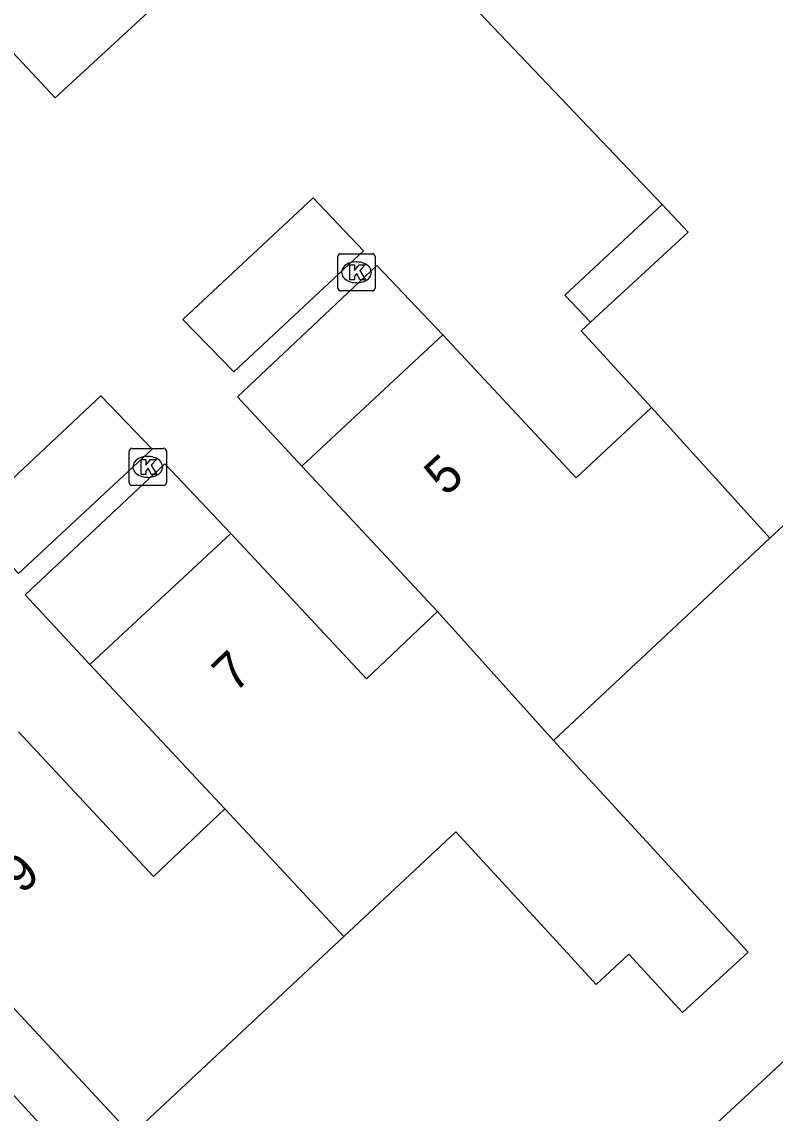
# Model space of a CAD drawing. Extents: x 160664 to 161506, y 382245 to 383288.
# Drawn here: x 160794.56 to 160814.82, y 383002.22 to 383031.57 of the extents above; entities that cross this region are included whole.
import ezdxf

# ---------------------------------------------------------------- set-up
doc = ezdxf.new("R2010")
doc.units = 0
for name, color, linetype in [('IMGEO_Fietspad_gesloten', 7, 'Continuous'), ('IMGEO_Kolk', 7, 'Continuous'), ('IMGEO_Pand', 7, 'Continuous'), ('IMGEO_Pand_nummerreeks', 7, 'Continuous'), ('IMGEO_Rijbaan_lokaal_open', 7, 'Continuous'), ('IMGEO_Voetpad_open', 7, 'Continuous')]:
    doc.layers.add(name, color=color, linetype=linetype)

msp = doc.modelspace()

# ---------------------------------------------------------------- linework, layer by layer
at = {"layer": 'IMGEO_Fietspad_gesloten'}
msp.add_lwpolyline([(160777.267, 383021.287), (160830.559, 382963.235), (160831.457, 382962.256), (160842.206, 382950.625)], dxfattribs=at)
at = {"layer": 'IMGEO_Kolk'}
for p, q in [((160803.057, 383024.411), (160803.057, 383025.263)), ((160803.132, 383025.337), (160803.984, 383025.337)), ((160804.058, 383025.263), (160804.058, 383024.411)), ((160803.545, 383025.117), (160803.57, 383025.117)), ((160803.984, 383024.337), (160803.132, 383024.337)), ((160803.568, 383024.557), (160803.543, 383024.557)), ((160797.443, 383019.177), (160797.443, 383020.029)), ((160797.518, 383020.103), (160798.37, 383020.103)), ((160798.444, 383020.029), (160798.444, 383019.177)), ((160797.931, 383019.883), (160797.956, 383019.883)), ((160797.954, 383019.323), (160797.929, 383019.323)), ((160798.37, 383019.103), (160797.518, 383019.103))]:
    msp.add_line(p, q, dxfattribs=at)
for points in [[(160803.057, 383024.411), (160803.057, 383025.263)], [(160803.132, 383025.337), (160803.984, 383025.337)], [(160804.058, 383025.263), (160804.058, 383024.411)], [(160803.378, 383025.037), (160803.501, 383025.037), (160803.501, 383024.886), (160803.631, 383025.037), (160803.795, 383025.037), (160803.649, 383024.886), (160803.802, 383024.637), (160803.65, 383024.637), (160803.565, 383024.801), (160803.501, 383024.734), (160803.501, 383024.637), (160803.378, 383024.637), (160803.378, 383025.037)], [(160803.984, 383024.337), (160803.132, 383024.337)], [(160797.443, 383019.177), (160797.443, 383020.029)], [(160797.518, 383020.103), (160798.37, 383020.103)], [(160798.444, 383020.029), (160798.444, 383019.177)], [(160797.764, 383019.803), (160797.887, 383019.803), (160797.887, 383019.652), (160798.017, 383019.803), (160798.181, 383019.803), (160798.035, 383019.652), (160798.188, 383019.403), (160798.036, 383019.403), (160797.951, 383019.567), (160797.887, 383019.5), (160797.887, 383019.403), (160797.764, 383019.403), (160797.764, 383019.803)], [(160798.37, 383019.103), (160797.518, 383019.103)]]:
    msp.add_lwpolyline(points, dxfattribs=at)
for centre, start, end in [((160803.134, 383025.261), 91.552, 178.448), ((160803.134, 383025.261), 91.552, 178.448), ((160803.982, 383025.261), 1.552, 88.448), ((160803.982, 383025.261), 1.552, 88.448), ((160803.134, 383024.413), 181.552, 268.448), ((160803.134, 383024.413), 181.552, 268.448), ((160803.982, 383024.413), 271.552, 358.448), ((160803.982, 383024.413), 271.552, 358.448), ((160797.52, 383020.027), 91.552, 178.448), ((160797.52, 383020.027), 91.552, 178.448), ((160798.368, 383020.027), 1.552, 88.448), ((160798.368, 383020.027), 1.552, 88.448), ((160797.52, 383019.179), 181.552, 268.448), ((160797.52, 383019.179), 181.552, 268.448), ((160798.368, 383019.179), 271.552, 358.448), ((160798.368, 383019.179), 271.552, 358.448)]:
    msp.add_arc(centre, 0.0765, start, end, dxfattribs=at)
for centre, major_axis, ratio, start_param, end_param in [((160803.544, 383024.837), (-0.387, 0.002), 0.722429, 4.712389, 7.853982), ((160803.569, 383024.837), (-0.39, 0.002), 0.717154, 1.570796, 4.712389), ((160797.93, 383019.603), (-0.387, 0.002), 0.722429, 4.712389, 7.853982), ((160797.955, 383019.603), (-0.39, 0.002), 0.717154, 1.570796, 4.712389)]:
    msp.add_ellipse(centre, major_axis=major_axis, ratio=ratio, start_param=start_param, end_param=end_param, dxfattribs=at)
at = {"layer": 'IMGEO_Pand'}
for points in [[(160798.881, 383040.207), (160811.78, 383026.66)], [(160814.674, 383017.683), (160815.277, 383018.246), (160815.072, 383018.458), (160826.068, 383028.889), (160823.688, 383031.397), (160824.264, 383031.944)], [(160811.78, 383026.66), (160812.484, 383025.921), (160809.853, 383023.497)], [(160809.853, 383023.497), (160809.603, 383023.267), (160811.497, 383021.202)], [(160805.883, 383023.157), (160802.091, 383019.626)], [(160811.497, 383021.202), (160809.467, 383019.307), (160805.883, 383023.157)], [(160811.497, 383021.202), (160814.674, 383017.683)], [(160802.091, 383019.626), (160805.737, 383015.711)], [(160800.177, 383017.817), (160796.388, 383014.288)], [(160805.737, 383015.711), (160803.824, 383013.902), (160800.177, 383017.817)], [(160808.861, 383012.25), (160814.674, 383017.683)], [(160805.737, 383015.711), (160808.861, 383012.25)], [(160796.388, 383014.288), (160800.016, 383010.405)], [(160800.016, 383010.405), (160798.097, 383008.591), (160794.468, 383012.481)], [(160808.861, 383012.25), (160811.566, 383009.303), (160812.633, 383008.14), (160814.093, 383006.549), (160812.326, 383004.927), (160810.88, 383006.502), (160810.002, 383005.682), (160808.935, 383006.845), (160806.23, 383009.792), (160803.219, 383006.978)], [(160803.219, 383006.978), (160800.016, 383010.405)], [(160797.509, 383001.643), (160790.688, 383008.954)], [(160803.219, 383006.978), (160797.729, 383001.848)]]:
    msp.add_lwpolyline(points, dxfattribs=at)
at = {"layer": 'IMGEO_Rijbaan_lokaal_open'}
for points in [[(160795.873, 383036.094), (160792.283, 383032.916), (160795.455, 383029.533), (160798.981, 383032.794), (160797.262, 383034.672)], [(160803.749, 383025.412), (160802.392, 383026.841), (160798.885, 383023.568), (160800.26, 383022.16), (160803.749, 383025.412)], [(160809.853, 383023.497), (160809.158, 383024.219), (160811.78, 383026.66)], [(160802.091, 383019.626), (160800.359, 383021.492), (160804.101, 383025.017), (160805.883, 383023.157)], [(160798.066, 383020.083), (160796.68, 383021.514), (160793.106, 383018.16), (160794.47, 383016.735), (160798.066, 383020.083)], [(160796.388, 383014.288), (160794.643, 383016.162), (160798.4, 383019.687), (160800.177, 383017.817)]]:
    msp.add_lwpolyline(points, dxfattribs=at)
at = {"layer": 'IMGEO_Voetpad_open'}
msp.add_lwpolyline([(160804.689, 382994.083), (160813.018, 383001.742), (160820.162, 383008.359), (160820.979, 383009.117), (160827.916, 383001.628), (160836.559, 382992.249), (160846.446, 382981.528), (160856.563, 382970.677), (160857.169, 382970.398), (160863.713, 382969.974), (160867.953, 382969.699), (160867.851, 382968.134), (160862.463, 382968.606)], dxfattribs=at)

# ---------------------------------------------------------------- texts
at = {"layer": 'IMGEO_Pand_nummerreeks'}
for s, rotation, p in [('5', 43.0066, (160805.964, 383018.786)), ('7', 43.8084, (160800.277, 383013.498)), ('9', 43.0119, (160794.563, 383008.084))]:
    msp.add_text(s, height=1, rotation=rotation, dxfattribs=at).set_placement(p)

doc.saveas('drawing.dxf')
